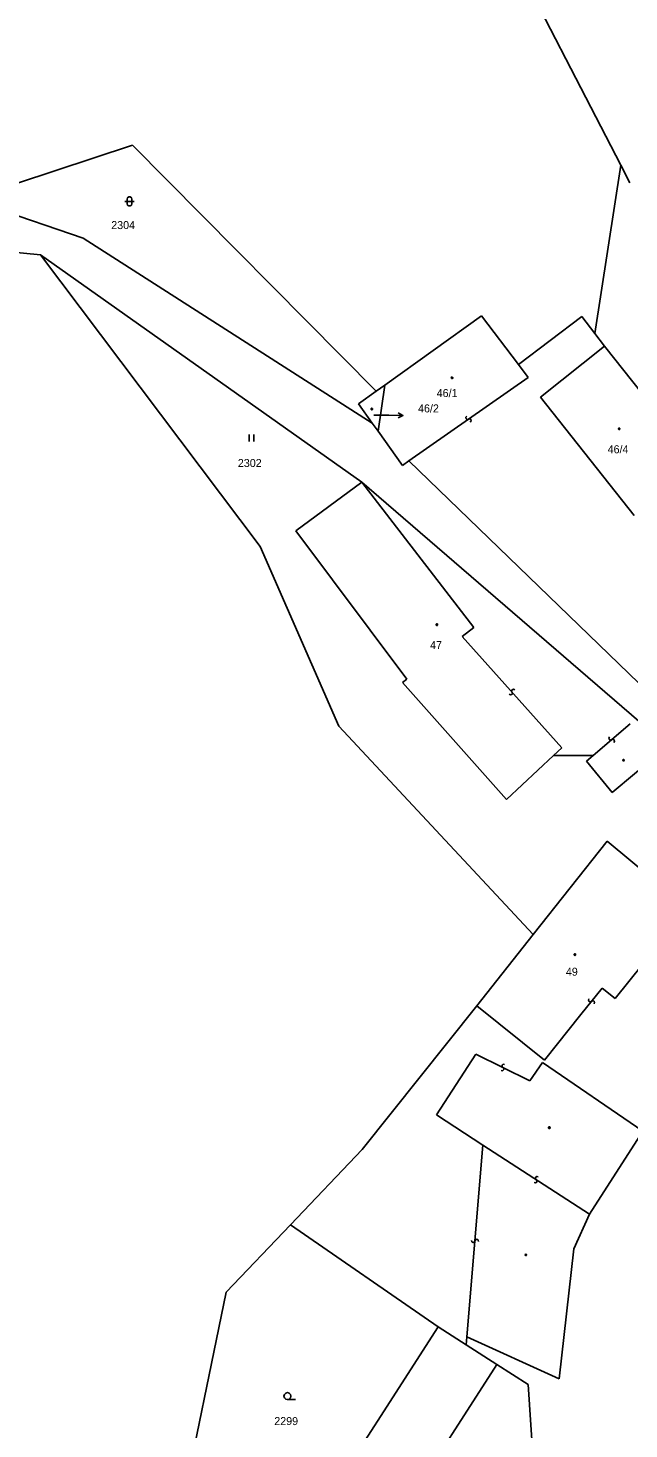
# Model space of a CAD drawing. Extents: x -747792 to -745414, y -1093712 to -1091463.
# Drawn here: x -746752.4 to -746688.5, y -1093115.1 to -1092966.2 of the extents above; entities that cross this region are included whole.
import ezdxf

# ---------------------------------------------------------------- set-up
doc = ezdxf.new("R2010")
doc.units = 0
for name, color, linetype in [('Pracovní_bod JDTM STC_VC', 7, 'Continuous'), ('Pracovní_bod JDTM STC_VC - výška', 7, 'Continuous'), ('Pracovní_bod JDTM STC_VC - číslo', 7, 'Continuous'), ('Pracovní_bod NN - výška', 7, 'Continuous'), ('Pracovní_bod polohopisu', 7, 'Continuous'), ('Pracovní_bod polohopisu - výška', 7, 'Continuous')]:
    doc.layers.add(name, color=color, linetype=linetype)

msp = doc.modelspace()

# ---------------------------------------------------------------- linework, layer by layer
at = {"layer": 'Pracovní_bod JDTM STC_VC - výška'}
for points in [[(-746707.29, -1093003.3), (-746707.24, -1093003.31), (-746707.22, -1093003.36), (-746707.21, -1093003.39), (-746707.22, -1093003.44), (-746707.26, -1093003.47), (-746707.29, -1093003.47), (-746707.33, -1093003.46), (-746707.36, -1093003.43), (-746707.38, -1093003.39), (-746707.36, -1093003.34), (-746707.33, -1093003.31)], [(-746715.81, -1093006.62), (-746715.76, -1093006.64), (-746715.74, -1093006.68), (-746715.73, -1093006.71), (-746715.74, -1093006.76), (-746715.78, -1093006.79), (-746715.81, -1093006.79), (-746715.85, -1093006.78), (-746715.89, -1093006.75), (-746715.9, -1093006.71), (-746715.89, -1093006.67), (-746715.84, -1093006.63)], [(-746689.51, -1093008.73), (-746689.46, -1093008.74), (-746689.44, -1093008.78), (-746689.43, -1093008.81), (-746689.44, -1093008.85), (-746689.48, -1093008.89), (-746689.51, -1093008.9), (-746689.55, -1093008.88), (-746689.58, -1093008.85), (-746689.59, -1093008.81), (-746689.58, -1093008.77), (-746689.54, -1093008.73)], [(-746708.9, -1093029.54), (-746708.85, -1093029.55), (-746708.83, -1093029.6), (-746708.82, -1093029.63), (-746708.83, -1093029.67), (-746708.86, -1093029.71), (-746708.9, -1093029.71), (-746708.95, -1093029.7), (-746708.98, -1093029.67), (-746708.99, -1093029.63), (-746708.98, -1093029.58), (-746708.94, -1093029.55)], [(-746689.02, -1093043.95), (-746688.98, -1093044.02), (-746689.02, -1093044.09), (-746689.11, -1093044.09), (-746689.16, -1093044.02), (-746689.11, -1093043.95)], [(-746694.23, -1093064.59), (-746694.18, -1093064.6), (-746694.16, -1093064.65), (-746694.15, -1093064.68), (-746694.16, -1093064.73), (-746694.2, -1093064.76), (-746694.23, -1093064.77), (-746694.27, -1093064.75), (-746694.3, -1093064.72), (-746694.32, -1093064.68), (-746694.3, -1093064.63), (-746694.26, -1093064.6)], [(-746696.91, -1093082.99), (-746696.86, -1093083.06), (-746696.91, -1093083.14), (-746696.99, -1093083.14), (-746697.04, -1093083.06), (-746696.99, -1093082.99)], [(-746699.4, -1093096.5), (-746699.35, -1093096.57), (-746699.4, -1093096.65), (-746699.48, -1093096.65), (-746699.53, -1093096.57), (-746699.48, -1093096.5)]]:
    msp.add_lwpolyline(points, close=True, dxfattribs=at)
at = {"layer": 'Pracovní_bod JDTM STC_VC - číslo'}
for points in [[(-746742.07, -1092984.65), (-746741.43, -1092984.65), (-746741.07, -1092984.65)], [(-746728.85, -1093009.42), (-746728.85, -1093010.17)], [(-746728.35, -1093010.17), (-746728.35, -1093009.42)], [(-746724.78, -1093111.96), (-746724.97, -1093111.91), (-746725.1, -1093111.77), (-746725.16, -1093111.58), (-746725.1, -1093111.4), (-746724.97, -1093111.26), (-746724.78, -1093111.21), (-746724.59, -1093111.26), (-746724.46, -1093111.4), (-746724.41, -1093111.58), (-746724.46, -1093111.77), (-746724.59, -1093111.91), (-746724.78, -1093111.96), (-746723.91, -1093111.96)]]:
    msp.add_lwpolyline(points, dxfattribs=at)
msp.add_lwpolyline([(-746741.82, -1092984.4), (-746741.77, -1092984.26), (-746741.65, -1092984.17), (-746741.49, -1092984.17), (-746741.36, -1092984.26), (-746741.32, -1092984.4), (-746741.32, -1092984.9), (-746741.36, -1092985.04), (-746741.49, -1092985.13), (-746741.65, -1092985.13), (-746741.77, -1092985.04), (-746741.82, -1092984.9)], close=True, dxfattribs=at)
at = {"layer": 'Pracovní_bod NN - výška'}
for points in [[(-746702.15, -1092956.05), (-746689.35, -1092980.81)], [(-746753.58, -1092982.75), (-746741.24, -1092978.69)], [(-746741.24, -1092978.69), (-746715.36, -1093004.83)], [(-746692.11, -1092998.69), (-746689.35, -1092980.81)], [(-746689.35, -1092980.81), (-746688.38, -1092982.68)], [(-746746.49, -1092988.54), (-746756.05, -1092985.29)], [(-746751.04, -1092990.33), (-746766.93, -1092988.76)], [(-746715.77, -1093008.21), (-746746.49, -1092988.54)], [(-746751.04, -1092990.33), (-746727.68, -1093021.32)], [(-746751.04, -1092990.33), (-746716.87, -1093014.48)], [(-746714.44, -1093004.17), (-746704.16, -1092996.82)], [(-746704.16, -1092996.82), (-746700.24, -1093001.99)], [(-746693.49, -1092996.88), (-746700.24, -1093001.99)], [(-746692.11, -1092998.69), (-746693.49, -1092996.88)], [(-746691.1, -1093000.02), (-746692.11, -1092998.69)], [(-746697.89, -1093005.45), (-746691.1, -1093000.02)], [(-746681.08, -1093012.59), (-746691.1, -1093000.02)], [(-746715.36, -1093004.83), (-746714.44, -1093004.17)], [(-746714.44, -1093004.17), (-746715.15, -1093009.07)], [(-746717.23, -1093006.17), (-746715.36, -1093004.83)], [(-746715.77, -1093008.21), (-746717.23, -1093006.17)], [(-746687.93, -1093018.03), (-746697.89, -1093005.45)], [(-746715.15, -1093009.07), (-746715.77, -1093008.21)], [(-746712.55, -1093012.7), (-746715.15, -1093009.07)], [(-746711.87, -1093012.22), (-746712.55, -1093012.7)], [(-746682.11, -1093040.96), (-746711.87, -1093012.22)], [(-746716.87, -1093014.48), (-746723.9, -1093019.65)], [(-746716.87, -1093014.48), (-746685.62, -1093041.42)], [(-746723.9, -1093019.65), (-746712.1, -1093035.41)], [(-746727.68, -1093021.32), (-746719.31, -1093040.4)], [(-746712.56, -1093035.77), (-746712.1, -1093035.41)], [(-746701.51, -1093048.21), (-746712.56, -1093035.77)], [(-746698.65, -1093062.54), (-746719.31, -1093040.4)], [(-746696.51, -1093043.53), (-746701.51, -1093048.21)], [(-746692.29, -1093043.52), (-746696.51, -1093043.53)], [(-746693.01, -1093044.13), (-746692.29, -1093043.52)], [(-746690.26, -1093047.45), (-746693.01, -1093044.13)], [(-746685.53, -1093043.5), (-746690.26, -1093047.45)], [(-746698.65, -1093062.54), (-746690.81, -1093052.63)], [(-746690.81, -1093052.63), (-746683.06, -1093059.07)], [(-746704.65, -1093070.13), (-746698.65, -1093062.54)], [(-746704.65, -1093070.13), (-746716.84, -1093085.38)], [(-746692.69, -1093092.24), (-746687, -1093083.45)], [(-746716.84, -1093085.38), (-746724.47, -1093093.39)], [(-746694.34, -1093095.95), (-746692.69, -1093092.24)], [(-746724.47, -1093093.39), (-746731.29, -1093100.55)], [(-746708.76, -1093104.21), (-746724.47, -1093093.39)], [(-746694.34, -1093095.95), (-746695.92, -1093109.76)], [(-746731.29, -1093100.55), (-746736.23, -1093124.49)], [(-746708.76, -1093104.21), (-746721.96, -1093124.78)], [(-746705.78, -1093106.12), (-746708.76, -1093104.21)], [(-746705.71, -1093105.27), (-746705.78, -1093106.12)], [(-746695.92, -1093109.76), (-746705.71, -1093105.27)], [(-746702.53, -1093108.21), (-746705.78, -1093106.12)], [(-746702.53, -1093108.21), (-746699.2, -1093110.35)], [(-746699.2, -1093110.35), (-746698.59, -1093119.45)]]:
    msp.add_lwpolyline(points, dxfattribs=at)
at = {"layer": 'Pracovní_bod polohopisu'}
for points in [[(-746700.24, -1093001.99), (-746699.21, -1093003.36)], [(-746699.21, -1093003.36), (-746711.87, -1093012.22)], [(-746705.35, -1093008.11), (-746705.25, -1093007.98), (-746705.29, -1093007.82), (-746705.43, -1093007.75), (-746705.67, -1093007.82), (-746705.8, -1093007.74), (-746705.83, -1093007.58), (-746705.73, -1093007.47)], [(-746704.97, -1093029.92), (-746716.87, -1093014.48)], [(-746706.2, -1093030.87), (-746704.97, -1093029.92)], [(-746706.2, -1093030.87), (-746695.61, -1093042.69)], [(-746700.61, -1093036.55), (-746700.75, -1093036.47), (-746700.9, -1093036.53), (-746700.96, -1093036.67), (-746700.86, -1093036.91), (-746700.92, -1093037.04), (-746701.08, -1093037.09), (-746701.2, -1093037.01)], [(-746692.29, -1093043.52), (-746688.34, -1093040.15)], [(-746690.54, -1093041.53), (-746690.62, -1093041.67), (-746690.57, -1093041.83), (-746690.43, -1093041.88), (-746690.19, -1093041.79), (-746690.05, -1093041.86), (-746690.01, -1093042.02), (-746690.09, -1093042.14)], [(-746695.61, -1093042.69), (-746696.51, -1093043.53)], [(-746684.28, -1093062.29), (-746689.94, -1093069.35)], [(-746693.59, -1093071.04), (-746691.34, -1093068.23)], [(-746689.94, -1093069.35), (-746691.34, -1093068.23)], [(-746704.65, -1093070.13), (-746697.46, -1093075.88)], [(-746692.74, -1093069.38), (-746692.8, -1093069.53), (-746692.71, -1093069.67), (-746692.56, -1093069.7), (-746692.35, -1093069.57), (-746692.2, -1093069.61), (-746692.13, -1093069.75), (-746692.19, -1093069.89)], [(-746697.46, -1093075.88), (-746693.59, -1093071.04)], [(-746704.76, -1093075.25), (-746708.95, -1093081.71)], [(-746699.01, -1093078.09), (-746704.76, -1093075.25)], [(-746702.07, -1093077), (-746701.92, -1093077.02), (-746701.79, -1093076.9), (-746701.8, -1093076.75), (-746701.97, -1093076.57), (-746701.97, -1093076.42), (-746701.84, -1093076.32), (-746701.7, -1093076.34)], [(-746699.01, -1093078.09), (-746697.68, -1093076.15)], [(-746697.68, -1093076.15), (-746687, -1093083.45)], [(-746708.95, -1093081.71), (-746704, -1093084.92)], [(-746704, -1093084.92), (-746705.71, -1093105.27)], [(-746704, -1093084.92), (-746692.69, -1093092.24)], [(-746698.12, -1093088.28), (-746698.27, -1093088.24), (-746698.41, -1093088.34), (-746698.42, -1093088.49), (-746698.27, -1093088.69), (-746698.29, -1093088.84), (-746698.43, -1093088.92), (-746698.57, -1093088.88)], [(-746704.48, -1093095.15), (-746704.52, -1093095), (-746704.67, -1093094.92), (-746704.81, -1093094.98), (-746704.92, -1093095.22), (-746705.06, -1093095.26), (-746705.2, -1093095.18), (-746705.23, -1093095.04)], [(-746712.28, -1093123.38), (-746702.53, -1093108.21)]]:
    msp.add_lwpolyline(points, dxfattribs=at)
at = {"layer": 'Pracovní_bod polohopisu - výška'}
for points in [[(-746715.59, -1093007.35), (-746714.01, -1093007.37)], [(-746712.51, -1093007.39), (-746714.01, -1093007.37)], [(-746713.01, -1093007.13), (-746712.51, -1093007.39), (-746713.01, -1093007.63)]]:
    msp.add_lwpolyline(points, dxfattribs=at)

# ---------------------------------------------------------------- texts
at = {"layer": 'Pracovní_bod JDTM STC_VC'}
for s, height, p in [('2304', 0.85, (-746743.51, -1092987.59)), ('46/1', 0.85, (-746708.92, -1093005.44)), ('46/2', 0.05, (-746715.67, -1093007.35)), ('46/4', 0.85, (-746690.75, -1093011.41)), ('2302', 0.85, (-746730.05, -1093012.87)), ('47', 0.85, (-746709.62, -1093032.21)), ('49', 0.85, (-746695.19, -1093066.92)), ('2299', 0.85, (-746726.18, -1093114.66))]:
    msp.add_text(s, height=height, dxfattribs=at).set_placement(p)
at = {"layer": 'Pracovní_bod polohopisu - výška'}
msp.add_text('46/2', height=0.85, dxfattribs=at).set_placement((-746710.9, -1093007.07))

doc.saveas('drawing.dxf')
